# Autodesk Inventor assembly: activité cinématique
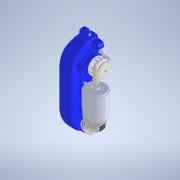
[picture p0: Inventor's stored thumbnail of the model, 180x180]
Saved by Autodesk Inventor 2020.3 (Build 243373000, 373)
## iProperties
Created: 2020-12
Part Number: activité cinématique
Document SubType Name: Assembly
Designer: M. Fichot
Author: M. Fichot
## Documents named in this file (7)
- D:\travail\année 2020-2021\2I2D\laveur de vitre\Lave vitre\4 Dossier Ressources\1 Modèles 3D Solidworks\activité cinématique.iam
- D:\travail\année 2020-2021\2I2D\laveur de vitre\Lave vitre\4 Dossier Ressources\1 Modèles 3D Solidworks\activité cinématique classe fixe.iam
- D:\travail\année 2020-2021\2I2D\laveur de vitre\Lave vitre\4 Dossier Ressources\1 Modèles 3D Solidworks\Roue Moteur.iam
- D:\travail\année 2020-2021\2I2D\laveur de vitre\Lave vitre\4 Dossier Ressources\1 Modèles 3D Solidworks\adaptation inventor\satellite.ipt
- D:\travail\année 2020-2021\2I2D\laveur de vitre\Lave vitre\4 Dossier Ressources\1 Modèles 3D Solidworks\adaptation inventor\porte sattelites inventor complet.iam
- D:\travail\année 2020-2021\2I2D\laveur de vitre\Lave vitre\4 Dossier Ressources\1 Modèles 3D Solidworks\adaptation inventor\roue dentée etagée.iam
- D:\travail\année 2020-2021\2I2D\laveur de vitre\Lave vitre\4 Dossier Ressources\1 Modèles 3D Solidworks\adaptation inventor\axe moteur cheville inventor.iam
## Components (7 placed, 6 different names)
1. activité cinématique classe fixe:1 [sub-assembly] — Logement:1, Logement:4, Logement:5
2. Roue Moteur:1 [sub-assembly] — Logement:1, Logement:2, Placage:1
3. Engrenage cylindrique2:1 — Logement:2
4. Engrenage cylindrique2:2 — Logement:3
5. porte sattelites inventor complet:1 [sub-assembly] — Placage:1, Logement:3
6. roue dentée etagée:1 [sub-assembly] — Logement:4
7. axe moteur cheville inventor:1 [sub-assembly] — Logement:5
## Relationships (6: Insert 5, Mate 1)
- Logement:1 [Insert]: activité cinématique classe fixe:1 ↔ Roue Moteur:1
- Logement:2 [Insert]: Roue Moteur:1 ↔ Engrenage cylindrique2:1
- Placage:1 [Mate]: Roue Moteur:1 ↔ porte sattelites inventor complet:1
- Logement:3 [Insert]: Engrenage cylindrique2:2 ↔ porte sattelites inventor complet:1
- Logement:4 [Insert]: activité cinématique classe fixe:1 ↔ roue dentée etagée:1
- Logement:5 [Insert]: activité cinématique classe fixe:1 ↔ axe moteur cheville inventor:1
